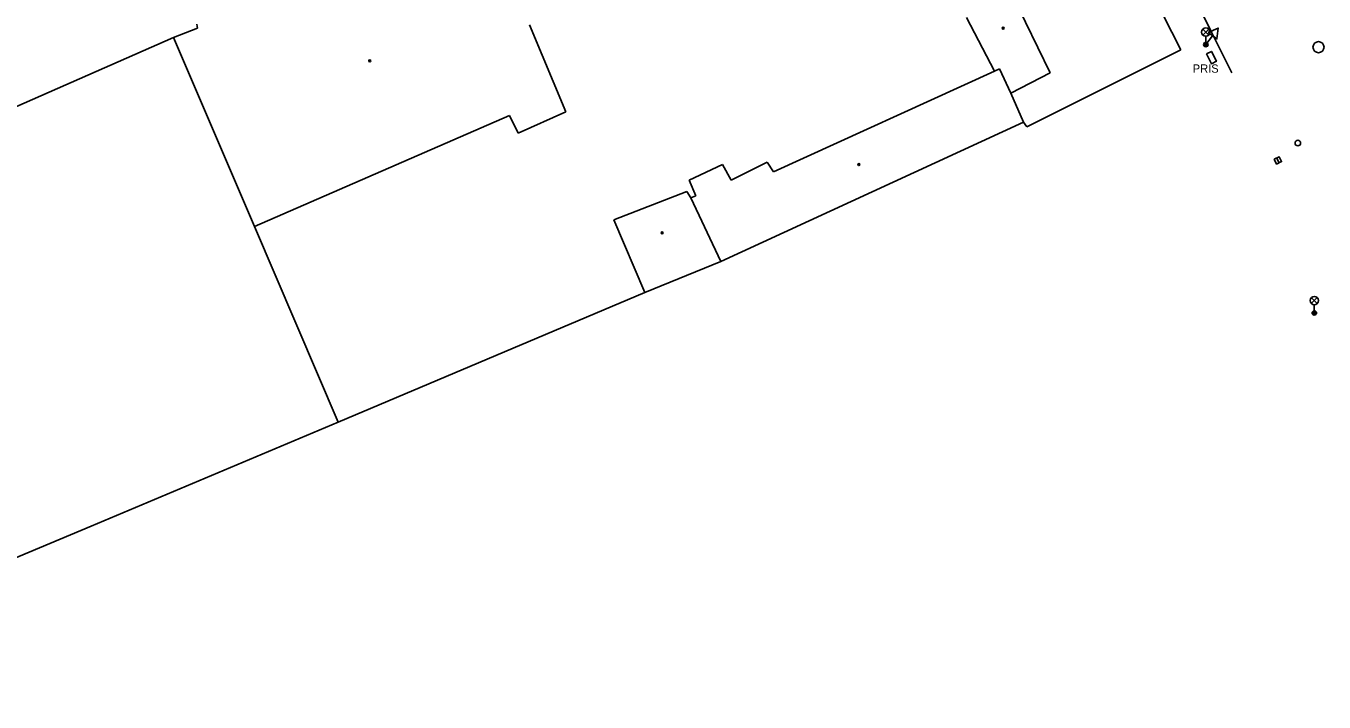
# Model space of a CAD drawing. Extents: x -598341 to -594502, y -1162301 to -1161406.
# Drawn here: x -597477.4 to -597359.9, y -1161909.2 to -1161848 of the extents above; entities that cross this region are included whole.
import ezdxf

# ---------------------------------------------------------------- set-up
doc = ezdxf.new("R2010")
doc.units = 0
for name, color, linetype in [('Vrstva 10', 7, 'Continuous'), ('Vrstva 11', 7, 'Continuous'), ('Vrstva 24', 7, 'Continuous'), ('Vrstva 27', 7, 'Continuous'), ('Vrstva 28', 7, 'Continuous'), ('Vrstva 33', 7, 'Continuous'), ('Vrstva 34', 7, 'Continuous'), ('Vrstva 39', 7, 'Continuous'), ('Vrstva 41', 7, 'Continuous'), ('Vrstva 5', 7, 'Continuous'), ('Vrstva 7', 7, 'Continuous')]:
    doc.layers.add(name, color=color, linetype=linetype)

msp = doc.modelspace()

# ---------------------------------------------------------------- linework, layer by layer
at = {"layer": 'Vrstva 10'}
msp.add_lwpolyline([(-597410.23, -1161767.56), (-597404.14, -1161785.35), (-597401.58, -1161792.6), (-597394.55, -1161806.99), (-597390.42, -1161815.33), (-597385.37, -1161822.82), (-597379.83, -1161831.05), (-597375.6, -1161837.3), (-597370.15, -1161848.42), (-597368.22, -1161852.29)], dxfattribs=at)
at = {"layer": 'Vrstva 11'}
msp.add_line((-597449.09, -1161883.93), (-597456.68, -1161866.19), dxfattribs=at)
at = {"layer": 'Vrstva 24'}
msp.add_lwpolyline([(-597370.53, -1161850.57), (-597370.08, -1161851.47), (-597369.63, -1161851.25), (-597370.08, -1161850.35)], close=True, dxfattribs=at)
at = {"layer": 'Vrstva 27'}
msp.add_line((-597364.18, -1161860), (-597363.96, -1161860.44), dxfattribs=at)
msp.add_lwpolyline([(-597364.41, -1161860.11), (-597364.18, -1161860.55), (-597363.73, -1161860.33), (-597363.96, -1161859.89)], close=True, dxfattribs=at)
msp.add_circle((-597360.39, -1161849.97), 0.5, dxfattribs=at)
at = {"layer": 'Vrstva 28'}
msp.add_circle((-597362.26, -1161858.65), 0.25, dxfattribs=at)
at = {"layer": 'Vrstva 33'}
for p, q in [((-597370.85, -1161848.88), (-597370.33, -1161848.35)), ((-597370.85, -1161848.35), (-597370.33, -1161848.88)), ((-597370.59, -1161848.99), (-597370.59, -1161849.74)), ((-597361.04, -1161873.17), (-597360.51, -1161872.64)), ((-597361.04, -1161872.64), (-597360.51, -1161873.17)), ((-597360.77, -1161873.28), (-597360.77, -1161874.03))]:
    msp.add_line(p, q, dxfattribs=at)
for centre, radius in [((-597370.59, -1161848.61), 0.375), ((-597370.59, -1161849.74), 0.2), ((-597370.59, -1161849.74), 0.145), ((-597370.59, -1161849.74), 0.0876), ((-597360.77, -1161872.91), 0.375), ((-597360.77, -1161874.03), 0.2), ((-597360.77, -1161874.03), 0.145), ((-597360.77, -1161874.03), 0.0876)]:
    msp.add_circle(centre, radius, dxfattribs=at)
at = {"layer": 'Vrstva 34'}
for p, q in [((-597370.79, -1161849.59), (-597370.39, -1161849.89)), ((-597369.98, -1161848.93), (-597370.59, -1161849.74))]:
    msp.add_line(p, q, dxfattribs=at)
msp.add_lwpolyline([(-597370.38, -1161848.63), (-597369.58, -1161849.23), (-597369.46, -1161848.24)], close=True, dxfattribs=at)
at = {"layer": 'Vrstva 39'}
for centre, radius in [((-597388.92, -1161848.25), 0.09), ((-597388.92, -1161848.25), 0.0398), ((-597446.25, -1161851.2), 0.09), ((-597446.25, -1161851.2), 0.0398), ((-597401.98, -1161860.6), 0.09), ((-597401.98, -1161860.6), 0.0398), ((-597419.79, -1161866.77), 0.09), ((-597419.79, -1161866.77), 0.0398)]:
    msp.add_circle(centre, radius, dxfattribs=at)
at = {"layer": 'Vrstva 5'}
for p, q in [((-597379.22, -1161837.68), (-597372.84, -1161850.2)), ((-597384.67, -1161852.29), (-597388.06, -1161845.31)), ((-597389.7, -1161852.15), (-597392.24, -1161847.28)), ((-597463.99, -1161849.11), (-597461.83, -1161848.25)), ((-597461.88, -1161847.9), (-597461.83, -1161848.25)), ((-597431.78, -1161847.94), (-597428.49, -1161855.81)), ((-597463.99, -1161849.11), (-597479.51, -1161855.9)), ((-597456.68, -1161866.19), (-597463.99, -1161849.11)), ((-597373.1, -1161850.33), (-597386.79, -1161857.17)), ((-597372.84, -1161850.2), (-597373.1, -1161850.33)), ((-597409.72, -1161861.25), (-597389.7, -1161852.15)), ((-597389.7, -1161852.15), (-597389.26, -1161851.92)), ((-597389.26, -1161851.92), (-597388.23, -1161854.13)), ((-597388.23, -1161854.13), (-597384.67, -1161852.29)), ((-597388.23, -1161854.13), (-597387.09, -1161856.76)), ((-597433.6, -1161856.17), (-597456.68, -1161866.19)), ((-597432.81, -1161857.74), (-597433.6, -1161856.17)), ((-597428.49, -1161855.81), (-597432.81, -1161857.74)), ((-597387.09, -1161856.76), (-597414.46, -1161869.37)), ((-597386.79, -1161857.17), (-597387.09, -1161856.76)), ((-597413.53, -1161862.01), (-597410.29, -1161860.37)), ((-597410.29, -1161860.37), (-597409.72, -1161861.25)), ((-597417.35, -1161862.02), (-597414.32, -1161860.59)), ((-597414.32, -1161860.59), (-597413.53, -1161862.01)), ((-597416.74, -1161863.42), (-597417.35, -1161862.02)), ((-597417.56, -1161863.04), (-597424.15, -1161865.6)), ((-597417.2, -1161863.62), (-597417.56, -1161863.04)), ((-597417.2, -1161863.62), (-597416.74, -1161863.42)), ((-597414.46, -1161869.37), (-597417.2, -1161863.62)), ((-597424.15, -1161865.6), (-597421.35, -1161872.18)), ((-597421.35, -1161872.18), (-597414.46, -1161869.37))]:
    msp.add_line(p, q, dxfattribs=at)
at = {"layer": 'Vrstva 7'}
for p, q in [((-597449.09, -1161883.93), (-597421.35, -1161872.18)), ((-597471.44, -1161893.33), (-597449.09, -1161883.93))]:
    msp.add_line(p, q, dxfattribs=at)
msp.add_lwpolyline([(-597471.44, -1161893.33), (-597509.45, -1161909.25)], dxfattribs=at)

# ---------------------------------------------------------------- texts
at = {"layer": 'Vrstva 41'}
msp.add_text('PRIS', height=0.75, dxfattribs=at).set_placement((-597371.77, -1161852.28))

doc.saveas('drawing.dxf')
